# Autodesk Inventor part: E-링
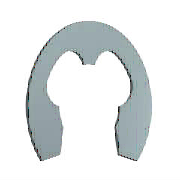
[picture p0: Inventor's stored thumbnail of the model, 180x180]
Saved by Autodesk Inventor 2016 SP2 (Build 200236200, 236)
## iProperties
IsCustomPart: 1
Created: 2012-02
Part Number: E-링
Material: 강철, 연강
Description: 일반용 테이퍼 및 줄어든 횡단면 리테이닝 링 - E-링 외부 시리즈 3CM1 리테이닝 링
Document SubType Name: Modeling
Standard: ANSI B27.7
Designer: mduedu
Standard Revision: 1999
Standards Organization: ANSI
Language: ko-KR
Size Designation: 6
Categories: <MemberInstance><Categories><Category DisplayName="샤프트 부품" InternalName="7f7aeb1f-a693-4053-b835-cee3144e0d98" Mnemonic="SHFT"><Category DisplayName="써클립" Inter
Density: 1 g/cm^3
Appearance: 파란색 - 벽 페인트 - 광택
Author: mduedu
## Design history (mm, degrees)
sketch "스케치1"
  geometry: L1 (-0.485, 0.024)-(0, 0.024) reference; L2 (-3.206, 0)-(3.486, 0) reference; L3 (-2.223, -3.946)-(2.223, -3.946); L4 (0, 1.949)-(0, -3.479) reference; L5 (-2.91, -2.006)-(-2.435, -2.006); L6 (-0.485, -0.066)-(-0.485, 0.405); L7 (0, 2.574)-(2.53, 2.574); L8 (-2.223, -3.946)-(-3.022, -6.291); L9 (0, -0.551)-(-1.278, -0.551); L10 (2.223, -3.946)-(3.022, -6.291); L11 (2.91, -2.006)-(2.435, -2.006); L12 (0.485, -0.066)-(0.485, 0.405); C1 r 3 at (0, -2.976); A1 r 2.425 centre (0, -2.976) between (-2.297, -2.199) and (-2.223, -3.946); A2 r 0.485 centre (0, -0.066) between (-0.485, -0.066) and (0.485, -0.066); A3 r 5.55 centre (0, -2.976) between (4.27, -6.521) and (-4.27, -6.521); A4 r 3.88 centre (0, -2.976) between (-0.97, 0.78) and (-3.424, -1.15); A5 r 0.388 centre (-0.873, 0.405) between (-0.485, 0.405) and (-0.97, 0.78); A6 r 0.582 centre (-2.91, -1.424) between (-3.424, -1.15) and (-2.91, -2.006); A7 r 0.145 centre (-2.435, -2.152) between (-2.297, -2.199) and (-2.435, -2.006); A8 r 0.727 centre (-3.711, -6.057) between (-4.27, -6.521) and (-3.022, -6.291); A9 r 0.727 centre (3.711, -6.057) between (3.022, -6.291) and (4.27, -6.521); A10 r 2.425 centre (0, -2.976) between (2.223, -3.946) and (2.297, -2.199); A11 r 0.145 centre (2.435, -2.152) between (2.435, -2.006) and (2.297, -2.199); A12 r 0.582 centre (2.91, -1.424) between (2.91, -2.006) and (3.424, -1.15); A13 r 3.88 centre (0, -2.976) between (3.424, -1.15) and (0.97, 0.78); A14 r 0.388 centre (0.873, 0.405) between (0.97, 0.78) and (0.485, 0.405); 1 further point
  constraints: 30 point on circle, 20 end point, 15 centre point, 13 symmetric about line, 12 tangent, 8 point on line, 4 parallel, 2 coincident, 2 horizontal, 1 concentric, 1 perpendicular, 1 vertical alignment, 9 other
  dimensions: "d0" = 6 diameter of C1 (= WD); "d3" = 0.97 distance from line of A1.centre L3 (= 0.2 x ND); "d4" = 0.485 radius of A2 (= 0.1 x ND); "d5" = 11.1 diameter of A3 (= SD2); "d8" = 3.88 radius of A4 (= 0.8 x ND); "d9" = 0.97 distance from line of A1.centre L5 (= 0.2 x ND); "d10" = 0.388 radius of A5 (= 0.08 x ND); "d11" = 0.582 radius of A6 (= 0.12 x ND); "d12" = 0.1455 radius of A7 (= 0.03 x ND); "d13" = 0.7275 radius of A8 (= 0.15 x ND); "d14" = 2.425 distance from line of A1.centre L9 (= 0.5 x ND); "d15" = 2.425 radius of A1 (= 0.5 x ND)
extrude "본체" new body sketch "스케치1" distance "d16" = 0.6 (= SD); taper "d17" = 0 deg
workaxis "Work Axis1"
workaxis "Work Axis2"
workplane "Work Plane1"
body "Solid1"
other parameters: "ND" = 4.85 [user parameter; used in 14 equation terms], "SD" = 0.6 [user parameter; used in 1 equation term], "WD" = 6 (= WDMIN) [user parameter; used in 1 equation term], "d1" = 7.76 (= 1.6 x ND), "d2" = 4.85 (= ND), "SD2" = 11.1 [user parameter; used in 1 equation term], "d6" = 4.85 (= ND), "d7" = 0.7275 (= 0.15 x ND), "d18" = 0, "d19" = 0, "d27" = 0, "d28" = 0, "WDMIN" = 6 [user parameter; used in 1 equation term], "SNB" = 0.7 [user parameter], "WDMAX" = 7 [user parameter], "BUBRMI" = 1.2 [user parameter]
